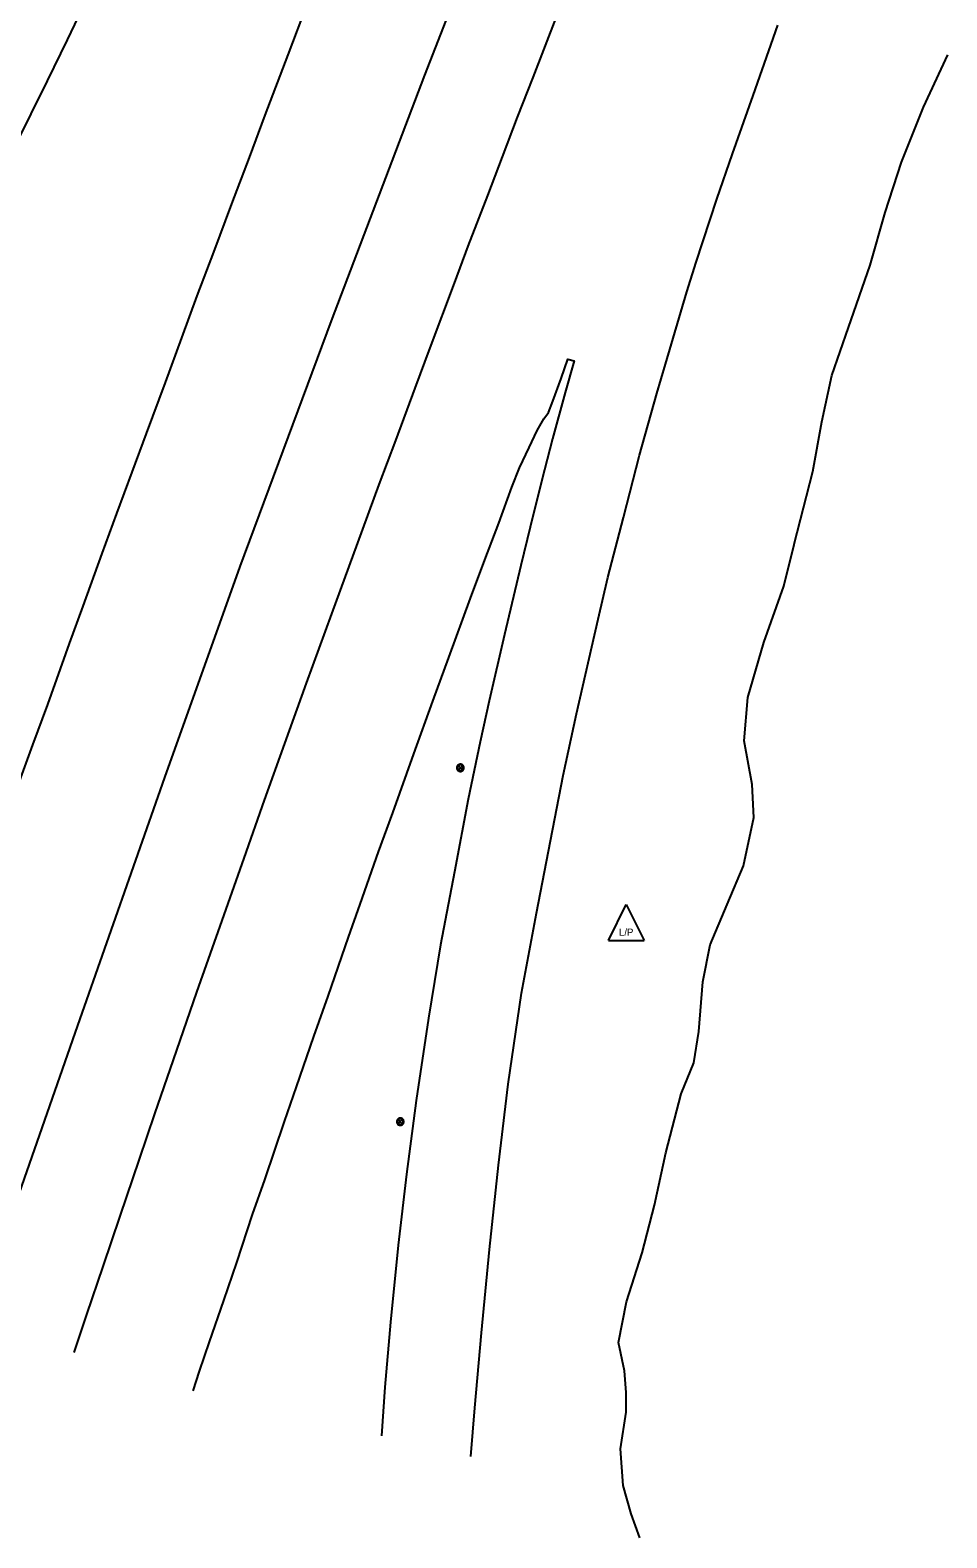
# Model space of a CAD drawing. Extents: x 2161152 to 2175754, y 602179 to 617749.
# Drawn here: x 2161408 to 2161664.5, y 602220 to 602641.4 of the extents above; entities that cross this region are included whole.
import ezdxf

# ---------------------------------------------------------------- set-up
doc = ezdxf.new("R2010")
doc.units = 0
for name, color, linetype in [('RD_EX_BldgApp_Post', 7, 'Continuous'), ('RD_EX_Fence_Other', 7, 'Continuous'), ('RD_EX_Road', 7, 'Continuous'), ('RD_EX_UT', 7, 'Continuous'), ('RD_EX_VEG', 7, 'Continuous')]:
    doc.layers.add(name, color=color, linetype=linetype)

msp = doc.modelspace()

# ---------------------------------------------------------------- linework, layer by layer
at = {"layer": 'RD_EX_BldgApp_Post'}
for p, q in [((2161528.95, 602434.63), (2161527.81, 602435.76)), ((2161527.81, 602434.63), (2161528.95, 602435.76)), ((2161512.13, 602335.72), (2161511, 602336.85)), ((2161511, 602335.72), (2161512.13, 602336.85))]:
    msp.add_line(p, q, dxfattribs=at)
for points in [[(2161529.38, 602435.2), (2161529.37, 602435.35), (2161529.33, 602435.51), (2161529.26, 602435.68), (2161529.16, 602435.83), (2161529.02, 602435.97), (2161528.85, 602436.08), (2161528.67, 602436.16), (2161528.48, 602436.19), (2161528.3, 602436.19), (2161528.13, 602436.16), (2161527.97, 602436.11), (2161527.84, 602436.04), (2161527.71, 602435.94), (2161527.59, 602435.82), (2161527.49, 602435.66), (2161527.42, 602435.49), (2161527.38, 602435.29), (2161527.38, 602435.1), (2161527.42, 602434.9), (2161527.49, 602434.73), (2161527.59, 602434.58), (2161527.71, 602434.45), (2161527.84, 602434.35), (2161527.97, 602434.28), (2161528.13, 602434.23), (2161528.3, 602434.2), (2161528.48, 602434.2), (2161528.67, 602434.24), (2161528.85, 602434.31), (2161529.02, 602434.42), (2161529.16, 602434.56), (2161529.26, 602434.71), (2161529.33, 602434.88), (2161529.37, 602435.04), (2161529.38, 602435.2)], [(2161529.18, 602435.2), (2161529.17, 602435.32), (2161529.14, 602435.45), (2161529.09, 602435.58), (2161529, 602435.7), (2161528.89, 602435.81), (2161528.76, 602435.9), (2161528.61, 602435.96), (2161528.46, 602435.99), (2161528.31, 602435.99), (2161528.18, 602435.97), (2161528.05, 602435.93), (2161527.95, 602435.87), (2161527.85, 602435.79), (2161527.75, 602435.69), (2161527.67, 602435.57), (2161527.61, 602435.43), (2161527.58, 602435.27), (2161527.58, 602435.12), (2161527.61, 602434.96), (2161527.67, 602434.82), (2161527.75, 602434.7), (2161527.85, 602434.6), (2161527.95, 602434.52), (2161528.05, 602434.46), (2161528.18, 602434.42), (2161528.31, 602434.4), (2161528.46, 602434.4), (2161528.61, 602434.43), (2161528.76, 602434.49), (2161528.89, 602434.58), (2161529, 602434.69), (2161529.09, 602434.81), (2161529.14, 602434.94), (2161529.17, 602435.07), (2161529.18, 602435.2)], [(2161512.57, 602336.28), (2161512.55, 602336.44), (2161512.51, 602336.6), (2161512.44, 602336.77), (2161512.34, 602336.92), (2161512.2, 602337.06), (2161512.04, 602337.17), (2161511.85, 602337.24), (2161511.67, 602337.28), (2161511.48, 602337.28), (2161511.31, 602337.25), (2161511.15, 602337.2), (2161511.02, 602337.13), (2161510.89, 602337.03), (2161510.78, 602336.9), (2161510.68, 602336.75), (2161510.6, 602336.58), (2161510.57, 602336.38), (2161510.57, 602336.19), (2161510.6, 602335.99), (2161510.68, 602335.82), (2161510.78, 602335.66), (2161510.89, 602335.54), (2161511.02, 602335.44), (2161511.15, 602335.37), (2161511.31, 602335.32), (2161511.48, 602335.29), (2161511.67, 602335.29), (2161511.85, 602335.33), (2161512.04, 602335.4), (2161512.2, 602335.51), (2161512.34, 602335.65), (2161512.44, 602335.8), (2161512.51, 602335.97), (2161512.55, 602336.13), (2161512.57, 602336.28)], [(2161512.37, 602336.28), (2161512.36, 602336.41), (2161512.32, 602336.54), (2161512.27, 602336.67), (2161512.18, 602336.79), (2161512.07, 602336.9), (2161511.94, 602336.99), (2161511.8, 602337.05), (2161511.64, 602337.08), (2161511.5, 602337.08), (2161511.36, 602337.06), (2161511.24, 602337.02), (2161511.13, 602336.96), (2161511.03, 602336.88), (2161510.93, 602336.78), (2161510.85, 602336.66), (2161510.8, 602336.52), (2161510.77, 602336.36), (2161510.77, 602336.21), (2161510.8, 602336.05), (2161510.85, 602335.91), (2161510.93, 602335.79), (2161511.03, 602335.69), (2161511.13, 602335.61), (2161511.24, 602335.55), (2161511.36, 602335.51), (2161511.5, 602335.49), (2161511.64, 602335.49), (2161511.8, 602335.52), (2161511.94, 602335.58), (2161512.07, 602335.67), (2161512.18, 602335.78), (2161512.27, 602335.9), (2161512.32, 602336.03), (2161512.36, 602336.16), (2161512.37, 602336.28)]]:
    msp.add_lwpolyline(points, dxfattribs=at)
at = {"layer": 'RD_EX_Fence_Other'}
msp.add_lwpolyline([(2161393.1, 602280.73), (2161404.32, 602314.28), (2161421.35, 602363.12), (2161445.71, 602432.45), (2161466.82, 602491.42), (2161492.35, 602560.11), (2161518.45, 602628.79), (2161543.97, 602694.29), (2161567.05, 602752.08), (2161594.98, 602821.59), (2161625.11, 602893.85), (2161655.74, 602966.15), (2161670.93, 603001.3), (2161686.85, 603037.69), (2161703.84, 603076.57), (2161723.47, 603119.8), (2161742.31, 603159.17), (2161753.57, 603183.42), (2161762.92, 603204.09), (2161772.85, 603227.48)], dxfattribs=at)
at = {"layer": 'RD_EX_Road'}
for points in [[(2161401.09, 602603.41), (2161408.31, 602617.97), (2161412.9, 602627.24), (2161418.46, 602638.69), (2161422.58, 602647.25)], [(2161404.32, 602429.36), (2161408.75, 602441.58), (2161412.93, 602452.88), (2161419.04, 602469.92), (2161422.82, 602480.39), (2161428.18, 602495.13), (2161432.26, 602506.27), (2161436.56, 602517.82), (2161440.54, 602528.59), (2161445.88, 602542.92), (2161450.45, 602555.35), (2161454.73, 602567.14), (2161459.45, 602579.36), (2161464.45, 602592.8), (2161469.36, 602605.78), (2161473.79, 602617.62), (2161480.18, 602634.46), (2161485.75, 602649)], [(2161555.07, 602644.86), (2161548.6, 602628.13), (2161544.28, 602617.01), (2161540.08, 602605.96), (2161535.96, 602595.15), (2161530.48, 602581), (2161526.6, 602570.62), (2161519.84, 602552.61), (2161515.6, 602541.28), (2161510.19, 602526.72), (2161505.59, 602514.42), (2161499.57, 602498.11), (2161492.28, 602478.24), (2161485.23, 602458.85), (2161479.15, 602442.01), (2161473.49, 602426.13), (2161467.77, 602409.9), (2161461.61, 602392.55), (2161454.55, 602372.47), (2161447.99, 602353.53), (2161442.81, 602338.45), (2161438.52, 602325.79), (2161433.13, 602309.9), (2161428.38, 602295.82), (2161423.83, 602282.37), (2161420.29, 602271.73)], [(2161531.29, 602242.68), (2161532.44, 602256.3), (2161534.25, 602277.23), (2161536.56, 602300.6), (2161539.03, 602324.11), (2161541.73, 602346.73), (2161545.49, 602372.18), (2161549.66, 602394.58), (2161552.99, 602411.89), (2161557.16, 602433.05), (2161560.84, 602450.26), (2161566.88, 602476.78), (2161569.64, 602488.34), (2161573.99, 602505.18), (2161578.44, 602522.54), (2161583.28, 602539.81), (2161585.72, 602548), (2161591.74, 602568.21), (2161594.35, 602576.56), (2161600.1, 602594.1), (2161604.52, 602606.79), (2161610.23, 602623.13), (2161617.17, 602642.8)], [(2161453.62, 602261.07), (2161455.41, 602266.51), (2161458.22, 602274.72), (2161462.18, 602286.3), (2161465.81, 602296.9), (2161470.26, 602310.32), (2161473.71, 602320.03), (2161479.18, 602336.31), (2161482.57, 602346.06), (2161487.39, 602360.11), (2161491.37, 602371.36), (2161497.09, 602387.86), (2161500.36, 602397.12), (2161505.48, 602411.72), (2161509.44, 602422.63), (2161515.4, 602439.13), (2161520.67, 602453.83), (2161525.13, 602466.03), (2161531.24, 602482.64), (2161535.19, 602493.32), (2161539.09, 602503.56), (2161542.8, 602513.61), (2161544.89, 602519.02), (2161547.57, 602524.75), (2161549.89, 602529.52), (2161551.71, 602532.69), (2161553.02, 602534.54), (2161554.22, 602537.64), (2161556.58, 602544.05), (2161558.43, 602549.44), (2161560.16, 602548.91), (2161557.69, 602540.12), (2161554.15, 602527.11), (2161551.19, 602515.59), (2161547.86, 602502.49), (2161545.26, 602491.74), (2161540.69, 602472.44), (2161536.38, 602453.88), (2161533.93, 602442.5), (2161530.58, 602426.39), (2161526.74, 602406.08), (2161522.82, 602385.69), (2161519.43, 602365.17), (2161516.02, 602342.21), (2161513.28, 602321.58), (2161511.01, 602301.76), (2161508.87, 602280.28), (2161507.26, 602262.12), (2161506.32, 602248.48)]]:
    msp.add_lwpolyline(points, dxfattribs=at)
at = {"layer": 'RD_EX_UT'}
for p, q in [((2161569.76, 602386.97), (2161574.76, 602396.97)), ((2161574.76, 602396.97), (2161579.76, 602386.97)), ((2161569.76, 602386.97), (2161579.76, 602386.97))]:
    msp.add_line(p, q, dxfattribs=at)
at = {"layer": 'RD_EX_VEG'}
msp.add_lwpolyline([(2161578.56, 602219.96), (2161576.18, 602226.7), (2161573.87, 602234.55), (2161573.15, 602244.85), (2161574.79, 602255.07), (2161574.73, 602260.55), (2161574.24, 602266.62), (2161572.58, 602274.55), (2161574.82, 602285.94), (2161579.23, 602299.65), (2161582.72, 602312.98), (2161585.82, 602327.57), (2161590.1, 602344.06), (2161593.69, 602352.75), (2161595.09, 602361.52), (2161596.18, 602375.34), (2161598.26, 602385.71), (2161603.03, 602396.98), (2161607.59, 602407.8), (2161610.46, 602421.34), (2161609.95, 602430.55), (2161607.72, 602442.71), (2161608.77, 602454.84), (2161613.22, 602470.26), (2161618.85, 602485.98), (2161621.74, 602497.63), (2161621.77, 602497.73), (2161626.92, 602518), (2161629.52, 602531.91), (2161632.31, 602544.85), (2161636.92, 602558.29), (2161643.03, 602575.69), (2161647.18, 602590.37), (2161651.73, 602604.51), (2161657.93, 602619.89), (2161664.74, 602634.5)], dxfattribs=at)

# ---------------------------------------------------------------- texts
at = {"layer": 'RD_EX_UT'}
msp.add_text('L/P', height=2, dxfattribs=at).set_placement((2161572.75, 602388.26))

doc.saveas('drawing.dxf')
